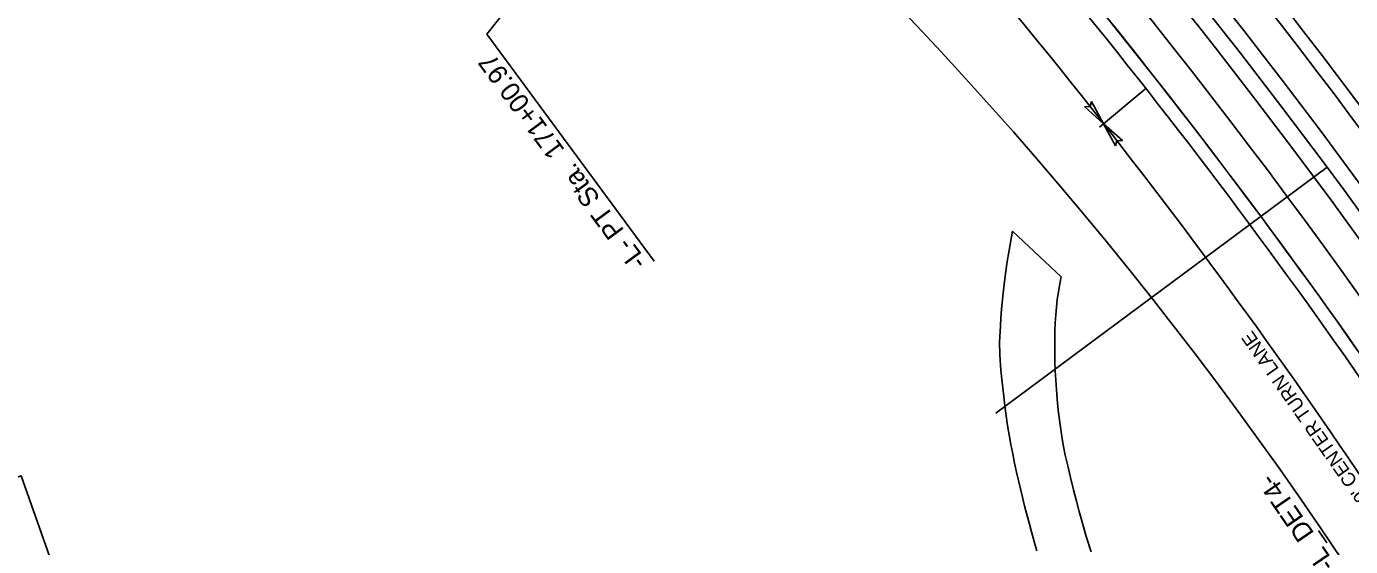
# Model space of a CAD drawing. Extents: x 472216 to 481979, y 489069 to 507339.
# Drawn here: x 475022 to 475503.5, y 502506.2 to 502695.3 of the extents above; entities that cross this region are included whole.
import ezdxf

# ---------------------------------------------------------------- set-up
doc = ezdxf.new("R2010")
doc.units = 0
for name, color, linetype in [('Exist Horizontal Alignment Point', 7, 'Continuous'), ('Old_Level_12', 7, 'Continuous'), ('Prop Drainage Structure Outlet Berm Ditch 850 10 CELL', 7, 'Continuous'), ('Prop Drainage Structure Pipe CSP 15in', 7, 'Continuous'), ('Prop Drainage Structure Pipe RCP 15in Class III Label', 7, 'Continuous'), ('Prop Drainage Structure Pipe RCP 24in Class III Label', 7, 'Continuous'), ('Prop Earthen Structure Head Ditch', 7, 'Continuous'), ('Prop Erosion Embankment Toe Protection CELL', 7, 'Continuous'), ('Prop Erosion Embankment Toe Protection Label', 7, 'Continuous'), ('Sheet Block Revision CELL', 7, 'Continuous'), ('Sheet Block Title CELL', 7, 'Continuous'), ('Sheet North Arrow Point CELL', 7, 'Continuous'), ('Sheet Profile Grid Major CELL', 7, 'Continuous')]:
    doc.layers.add(name, color=color, linetype=linetype)

msp = doc.modelspace()

# ---------------------------------------------------------------- linework, layer by layer
at = {"layer": 'Exist Horizontal Alignment Point'}
msp.add_lwpolyline([(474231.25, 502253.74), (475020.13, 502531.9), (475058.67, 502422.6), (474269.79, 502144.44)], close=True, dxfattribs=at)
at = {"layer": 'Old_Level_12'}
for p, q in [((475316.69, 502854.48), (475189.46, 502692.51)), ((475189.46, 502692.51), (475250.35, 502610.05))]:
    msp.add_line(p, q, dxfattribs=at)
at = {"layer": 'Prop Drainage Structure Outlet Berm Ditch 850 10 CELL'}
for points in [[(475409.38, 502668.02), (475413.73, 502659.99), (475406.87, 502666.11), (475408.84, 502666.2)], [(475418.05, 502651.95), (475413.73, 502659.99), (475420.56, 502653.85), (475418.6, 502653.77)]]:
    msp.add_lwpolyline(points, close=True, dxfattribs=at)
at = {"layer": 'Prop Drainage Structure Pipe RCP 15in Class III Label'}
for radius in [2336, 2324]:
    msp.add_arc((473624.13, 501255.38), radius, 25.1104, 43.06144, dxfattribs=at)
at = {"layer": 'Prop Drainage Structure Pipe RCP 24in Class III Label'}
for radius, start, end in [(2348, 26.36139, 43.06144), (2300, 33.44784, 43.06537), (2300, 33.44784, 43.06144)]:
    msp.add_arc((473624.13, 501255.38), radius, start, end, dxfattribs=at)
at = {"layer": 'Prop Earthen Structure Head Ditch'}
msp.add_line((475398.3, 502604.3), (475380.67, 502620.9), dxfattribs=at)
for points in [[(475380.67, 502620.9), (475380.3, 502618.83), (475379.32, 502613.3), (475378.73, 502609.86), (475378.18, 502606.33), (475377.67, 502602.55), (475377.2, 502598.34), (475376.65, 502592.51), (475376.4, 502589.41), (475376.2, 502586.39), (475375.94, 502580.71), (475375.95, 502575.9), (475376.31, 502570.38), (475376.69, 502567.1), (475377.07, 502563.89), (475377.45, 502560.74), (475377.87, 502557.36), (475378.34, 502553.75), (475378.85, 502550.22), (475379.4, 502546.82), (475380.01, 502543.37), (475380.68, 502539.88), (475381.37, 502536.53), (475382.07, 502533.33), (475382.76, 502530.25), (475383.46, 502527.26), (475384.21, 502524.18), (475385.03, 502521.03), (475385.83, 502517.91), (475386.64, 502514.81), (475387.51, 502511.53), (475388.47, 502508.08), (475389.44, 502504.7)], [(475409.19, 502504.34), (475407.42, 502509.85), (475405.77, 502515.55), (475404.85, 502518.92), (475403.83, 502522.71), (475402.78, 502526.87), (475401.71, 502531.31), (475400.71, 502535.53), (475399.8, 502539.4), (475399.11, 502542.64), (475398.62, 502545.41), (475397.8, 502551.34), (475397.27, 502555.85), (475396.87, 502559.77), (475396.57, 502563.32), (475396.33, 502566.73), (475396.16, 502570.11), (475396.05, 502573.57), (475396, 502577.15), (475396, 502580.86), (475396.06, 502584.44), (475396.16, 502587.62), (475396.33, 502590.52), (475396.9, 502596.03), (475397.77, 502601.81), (475398.3, 502604.3)]]:
    msp.add_lwpolyline(points, dxfattribs=at)
at = {"layer": 'Prop Erosion Embankment Toe Protection CELL'}
for radius, start, end in [(2353, 25.8357, 43.06144), (2295, 33.45244, 43.06537)]:
    msp.add_arc((473624.13, 501255.38), radius, start, end, dxfattribs=at)
at = {"layer": 'Prop Erosion Embankment Toe Protection Label'}
msp.add_arc((473624.13, 501255.38), 2312, 25.1104, 43.06144, dxfattribs=at)
at = {"layer": 'Sheet Block Revision CELL'}
msp.add_line((475429.12, 502672.77), (475412.19, 502658.72), dxfattribs=at)
for start, end in [(38.12758, 43.37358), (33.45244, 38.12758)]:
    msp.add_arc((473624.13, 501255.38), 2275, start, end, dxfattribs=at)
at = {"layer": 'Sheet Block Title CELL'}
msp.add_line((475374.56, 502554.76), (475495, 502644.16), dxfattribs=at)
at = {"layer": 'Sheet North Arrow Point CELL'}
for centre, radius, start, end in [((474253.94, 501667.1), 1500, 26.80164, 58.77708), ((473624.13, 501255.38), 2330, 23.81642, 43.37358)]:
    msp.add_arc(centre, radius, start, end, dxfattribs=at)

# ---------------------------------------------------------------- texts
at = {"layer": 'Old_Level_12'}
msp.add_text('-L- PT Sta.  171+00.97', height=7, rotation=126.4463, dxfattribs=at).set_placement((475247.95, 502609.88))
at = {"layer": 'Prop Drainage Structure Pipe CSP 15in'}
msp.add_text("530' CENTER TURN LANE", height=5, rotation=125.0735, dxfattribs=at).set_placement((475514.5, 502518.32))
at = {"layer": 'Sheet Profile Grid Major CELL'}
msp.add_text('-L_DET4-', height=7, rotation=124.406, dxfattribs=at).set_placement((475498.19, 502499.84))

doc.saveas('drawing.dxf')
